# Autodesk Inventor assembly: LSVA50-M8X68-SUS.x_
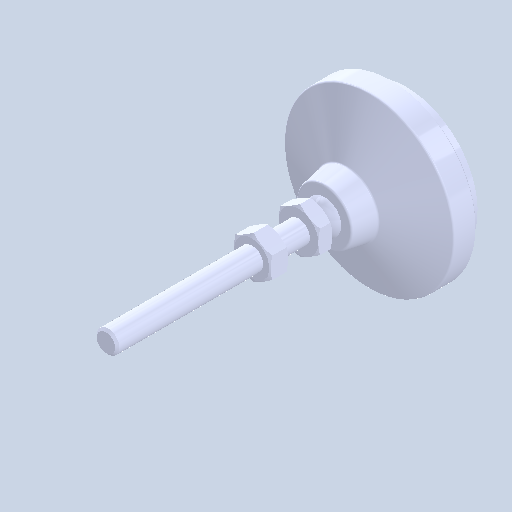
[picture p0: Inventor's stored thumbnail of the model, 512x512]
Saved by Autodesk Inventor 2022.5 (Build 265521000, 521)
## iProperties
Created: 2024-08
Part Number: LSVA50-M8X68-SUS.x_
Document SubType Name: Assembly
Designer: ImaoCorp
Author: ImaoCorp
Sending System: SOLIDWORKS 2022-2022290
MC: AMD64
MC_MODEL: Intel64 Family 6 Model 60 Stepping 3, GenuineIntel
OS: Windows_NT
FRU: Parasolid Version 33.1, build 260,  4-25-2022
FORMAT: text
GUISE: transmit
KEY: FILELSVA50-M8X68-SUS.x_t
DATE: Fri Aug 23 16:08:55 2024
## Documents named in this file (4)
- X:\14_SW2022-Inv2022\06_2024-10新製品(SME)\ELS_データ\l\lsva50-m8x68-sus\LSVA50-M8X68-SUS.x_.iam
- X:\14_SW2022-Inv2022\06_2024-10新製品(SME)\ELS_データ\l\lsva50-m8x68-sus\LSVA50-M8X68-SUS_01.ipt
- X:\14_SW2022-Inv2022\06_2024-10新製品(SME)\ELS_データ\l\lsva50-m8x68-sus\LSVA50-M8X68-SUS_02.ipt
- X:\14_SW2022-Inv2022\06_2024-10新製品(SME)\ELS_データ\l\lsva50-m8x68-sus\LSVA50-M8X68-SUS_03.ipt
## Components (3 placed, 3 different names)
1. LSVA50-M8X68-SUS_01
2. LSVA50-M8X68-SUS_02
3. LSVA50-M8X68-SUS_03
